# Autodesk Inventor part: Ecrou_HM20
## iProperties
Library Location: C:\Program Files\Autodesk\Inventor 6\content
Library: local
SubLibrary: ISO
Family: 46
Member: 210
Member Major Revision: 1
Member Minor Revision: 1
Comments: To add or edit properties for Autodesk Inventor files, use iProperties.
Created: 2008-02
Part Number: Ecrou_HM20
Vendor: Autodesk Inc.
Document SubType Name: Modeling
Designer: Pascal
Description: Hex Nut with Torque Part
Standard: ISO 7041 M20
Alert: To add or edit properties for Autodesk Inventor files, use iProperties.
Control State: 0
Master: False
Checked Out: False
Shininess: 64.0
Length Units: 11269
Angle Units: 11279
Time Units: 11290
Mass Units: 11283
Length Display Precision: 3
Angle Display Precision: 2
Compacted: True
EGR: 1
Density: 0.0
Volumn: 0.0
Area: 0.0
PropertySet Name: Model Information
Author: Pascal
Revision Number: 1
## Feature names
1. Body [Extrusion]
2. Ring [Extrusion]
3. Chamfer1 [Revolution]
4. Thread [Hole]
5. Chamfer2
6. Chamfer3
